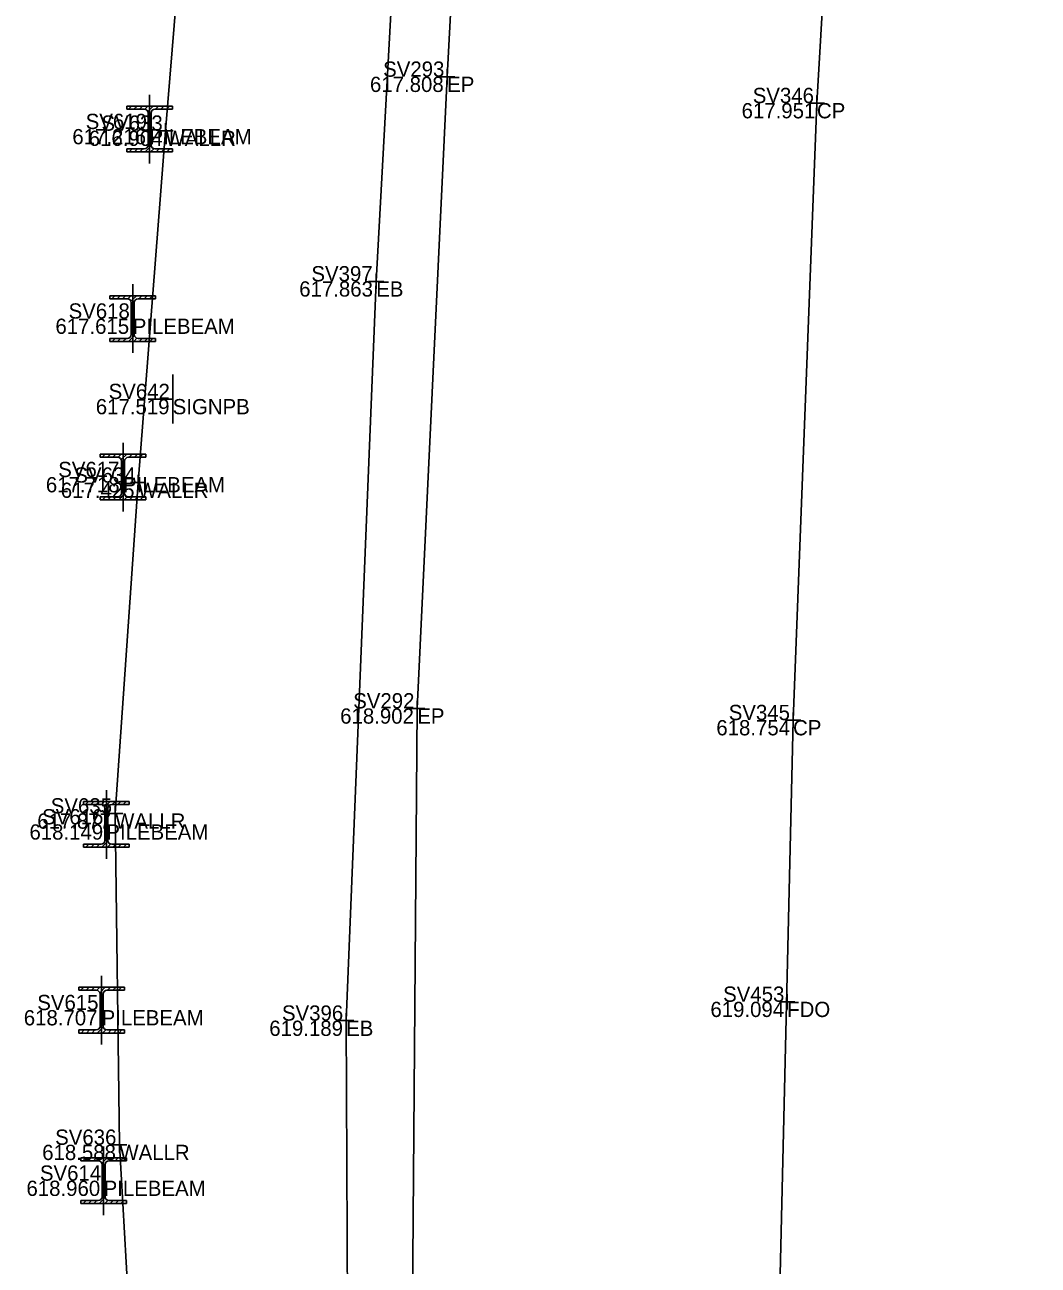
# Model space of a CAD drawing. Extents: x -2 to 1979875, y -2 to 232027.
# Drawn here: x 1978723.28 to 1978756.51, y 230801.2 to 230841.86 of the extents above; entities that cross this region are included whole.
import ezdxf

# ---------------------------------------------------------------- set-up
doc = ezdxf.new("R2010")
doc.units = 0
for name, color, linetype in [('_CIVIL_CONSTRUCTION', 7, 'Continuous'), ('GE_P_Alignment_500_Curve_Data', 7, 'Continuous'), ('GE_X_Alignment', 7, 'Continuous'), ('GE_X_Alignment_1000_Curve_Data', 7, 'Continuous'), ('GE_X_Alignment_1000_Stations', 7, 'Continuous'), ('GE_X_Alignment_100_Curve_Data', 7, 'Continuous'), ('GE_X_Alignment_100_Stations', 7, 'Continuous'), ('GE_X_Alignment_500_Stations', 7, 'Continuous'), ('GT_X_Piling_Cells', 7, 'Continuous'), ('RD_X_Wall', 7, 'Continuous'), ('SC_Scratch1', 7, 'Continuous')]:
    doc.layers.add(name, color=color, linetype=linetype)

msp = doc.modelspace()

# ---------------------------------------------------------------- linework, layer by layer
at = {"layer": 'GE_P_Alignment_500_Curve_Data'}
for p, q in [((1978748.027, 230809.838), (1978748.527, 230809.838)), ((1978748.277, 230810.088), (1978748.277, 230809.588)), ((1978748.277, 230809.838), (1978748.277, 230809.838))]:
    msp.add_line(p, q, dxfattribs=at)
at = {"layer": 'GE_X_Alignment_1000_Curve_Data'}
msp.add_lwpolyline([(1978771.368, 230686.901), (1978762.945, 230707.808), (1978756.184, 230729.845), (1978751.49, 230752.309), (1978748.994, 230772.916), (1978748.08, 230796.049), (1978747.937, 230796.247), (1978748.471, 230819.071), (1978749.254, 230839.296), (1978750.532, 230861.092), (1978751.977, 230883.907), (1978753.538, 230907.259), (1978755.272, 230931.005), (1978756.708, 230952.708), (1978758.182, 230974.871), (1978759.598, 230998.872), (1978761.121, 231023.464)], dxfattribs=at)
at = {"layer": 'GE_X_Alignment_1000_Stations'}
msp.add_lwpolyline([(1978772.336, 230656.843), (1978763.559, 230673.456), (1978754.964, 230693.186), (1978747.098, 230715.323), (1978742.189, 230735.369), (1978738.656, 230754.308), (1978736.533, 230775.816), (1978735.988, 230798.596), (1978736.151, 230819.454), (1978737.13, 230840.16), (1978738.357, 230863.144), (1978739.649, 230887.098), (1978741.331, 230908.702), (1978742.827, 230930.869), (1978744.275, 230952.773), (1978745.794, 230976.041), (1978747.11, 230998.611), (1978748.464, 231019.612), (1978749.988, 231043.472)], dxfattribs=at)
at = {"layer": 'GE_X_Alignment_100_Curve_Data'}
for p, q in [((1978737.13, 230840.41), (1978737.13, 230839.91)), ((1978736.88, 230840.16), (1978737.38, 230840.16)), ((1978737.13, 230840.16), (1978737.13, 230840.16)), ((1978749.254, 230839.546), (1978749.254, 230839.046)), ((1978749.004, 230839.296), (1978749.504, 230839.296)), ((1978749.254, 230839.296), (1978749.254, 230839.296)), ((1978727.645, 230838.391), (1978728.145, 230838.391)), ((1978727.895, 230838.641), (1978727.895, 230838.141)), ((1978727.895, 230838.391), (1978727.895, 230838.391)), ((1978734.555, 230833.453), (1978735.055, 230833.453)), ((1978734.805, 230833.703), (1978734.805, 230833.203)), ((1978734.805, 230833.453), (1978734.805, 230833.453)), ((1978726.998, 230827.105), (1978726.998, 230826.605)), ((1978726.748, 230826.855), (1978727.248, 230826.855)), ((1978726.998, 230826.855), (1978726.998, 230826.855)), ((1978736.151, 230819.704), (1978736.151, 230819.204)), ((1978735.901, 230819.454), (1978736.401, 230819.454)), ((1978736.151, 230819.454), (1978736.151, 230819.454)), ((1978748.471, 230819.321), (1978748.471, 230818.821)), ((1978748.221, 230819.071), (1978748.721, 230819.071)), ((1978748.471, 230819.071), (1978748.471, 230819.071)), ((1978725.994, 230816.011), (1978726.494, 230816.011)), ((1978726.244, 230816.261), (1978726.244, 230815.761)), ((1978726.244, 230816.011), (1978726.244, 230816.011)), ((1978733.819, 230809.469), (1978733.819, 230808.969)), ((1978733.569, 230809.219), (1978734.069, 230809.219)), ((1978733.819, 230809.219), (1978733.819, 230809.219)), ((1978726.384, 230805.4), (1978726.384, 230804.9)), ((1978726.134, 230805.15), (1978726.634, 230805.15)), ((1978726.384, 230805.15), (1978726.384, 230805.15))]:
    msp.add_line(p, q, dxfattribs=at)
at = {"layer": 'GE_X_Alignment_500_Stations'}
for p, q in [((1978728.132, 230830.395), (1978728.132, 230828.795)), ((1978728.132, 230829.595), (1978727.332, 230829.595))]:
    msp.add_line(p, q, dxfattribs=at)
at = {"layer": 'GT_X_Piling_Cells'}
for p, q in [((1978727.374, 230837.32), (1978727.374, 230839.57)), ((1978728.124, 230839.195), (1978726.624, 230839.195)), ((1978726.624, 230839.195), (1978726.624, 230839.095)), ((1978726.624, 230839.095), (1978727.199, 230839.095)), ((1978726.687, 230839.095), (1978726.787, 230839.195)), ((1978726.863, 230839.095), (1978726.963, 230839.195)), ((1978727.04, 230839.095), (1978727.14, 230839.195)), ((1978727.216, 230839.094), (1978727.317, 230839.195)), ((1978727.315, 230839.016), (1978727.494, 230839.195)), ((1978727.549, 230839.095), (1978728.124, 230839.095)), ((1978727.57, 230839.095), (1978727.67, 230839.195)), ((1978727.747, 230839.095), (1978727.847, 230839.195)), ((1978727.924, 230839.095), (1978728.024, 230839.195)), ((1978728.101, 230839.095), (1978728.124, 230839.118)), ((1978728.124, 230839.095), (1978728.124, 230839.195)), ((1978727.324, 230838.97), (1978727.324, 230837.92)), ((1978727.324, 230838.849), (1978727.424, 230838.949)), ((1978727.324, 230838.672), (1978727.424, 230838.772)), ((1978727.424, 230837.92), (1978727.424, 230838.97)), ((1978727.324, 230838.495), (1978727.424, 230838.595)), ((1978727.324, 230838.318), (1978727.424, 230838.418)), ((1978727.374, 230838.445), (1978727.374, 230838.445)), ((1978727.231, 230837.695), (1978727.427, 230837.891)), ((1978727.324, 230838.141), (1978727.424, 230838.241)), ((1978727.324, 230837.965), (1978727.424, 230838.065)), ((1978727.199, 230837.795), (1978726.624, 230837.795)), ((1978726.624, 230837.795), (1978726.624, 230837.695)), ((1978726.624, 230837.695), (1978728.124, 230837.695)), ((1978726.701, 230837.695), (1978726.801, 230837.795)), ((1978726.878, 230837.695), (1978726.978, 230837.795)), ((1978727.054, 230837.695), (1978727.154, 230837.795)), ((1978727.408, 230837.695), (1978727.513, 230837.8)), ((1978728.124, 230837.795), (1978727.549, 230837.795)), ((1978727.585, 230837.695), (1978727.685, 230837.795)), ((1978727.761, 230837.695), (1978727.861, 230837.795)), ((1978727.938, 230837.695), (1978728.038, 230837.795)), ((1978728.115, 230837.695), (1978728.124, 230837.704)), ((1978728.124, 230837.695), (1978728.124, 230837.795)), ((1978727.572, 230832.981), (1978726.072, 230832.981)), ((1978726.072, 230832.981), (1978726.072, 230832.881)), ((1978726.135, 230832.881), (1978726.235, 230832.981)), ((1978726.311, 230832.881), (1978726.411, 230832.981)), ((1978726.488, 230832.881), (1978726.588, 230832.981)), ((1978726.664, 230832.88), (1978726.765, 230832.981)), ((1978726.763, 230832.802), (1978726.942, 230832.981)), ((1978726.822, 230831.106), (1978726.822, 230833.356)), ((1978727.018, 230832.881), (1978727.118, 230832.981)), ((1978727.195, 230832.881), (1978727.295, 230832.981)), ((1978727.372, 230832.881), (1978727.472, 230832.981)), ((1978727.572, 230832.881), (1978727.572, 230832.981)), ((1978726.072, 230832.881), (1978726.647, 230832.881)), ((1978726.772, 230832.756), (1978726.772, 230831.706)), ((1978726.772, 230832.635), (1978726.872, 230832.735)), ((1978726.872, 230831.706), (1978726.872, 230832.756)), ((1978726.997, 230832.881), (1978727.572, 230832.881)), ((1978727.549, 230832.881), (1978727.572, 230832.904)), ((1978726.772, 230832.458), (1978726.872, 230832.558)), ((1978726.772, 230832.281), (1978726.872, 230832.381)), ((1978726.772, 230832.104), (1978726.872, 230832.204)), ((1978726.822, 230832.231), (1978726.822, 230832.231)), ((1978726.772, 230831.927), (1978726.872, 230832.027)), ((1978726.772, 230831.751), (1978726.872, 230831.851)), ((1978726.647, 230831.581), (1978726.072, 230831.581)), ((1978726.072, 230831.581), (1978726.072, 230831.481)), ((1978726.072, 230831.481), (1978727.572, 230831.481)), ((1978726.149, 230831.481), (1978726.249, 230831.581)), ((1978726.326, 230831.481), (1978726.426, 230831.581)), ((1978726.502, 230831.481), (1978726.602, 230831.581)), ((1978726.679, 230831.481), (1978726.875, 230831.677)), ((1978726.856, 230831.481), (1978726.961, 230831.586)), ((1978727.572, 230831.581), (1978726.997, 230831.581)), ((1978727.033, 230831.481), (1978727.133, 230831.581)), ((1978727.209, 230831.481), (1978727.309, 230831.581)), ((1978727.386, 230831.481), (1978727.486, 230831.581)), ((1978727.563, 230831.481), (1978727.572, 230831.49)), ((1978727.572, 230831.481), (1978727.572, 230831.581)), ((1978726.504, 230825.912), (1978726.504, 230828.162)), ((1978727.254, 230827.787), (1978725.754, 230827.787)), ((1978725.754, 230827.787), (1978725.754, 230827.687)), ((1978725.817, 230827.687), (1978725.917, 230827.787)), ((1978725.993, 230827.687), (1978726.093, 230827.787)), ((1978726.17, 230827.687), (1978726.27, 230827.787)), ((1978726.346, 230827.686), (1978726.447, 230827.787)), ((1978726.445, 230827.608), (1978726.624, 230827.787)), ((1978726.7, 230827.687), (1978726.8, 230827.787)), ((1978726.877, 230827.687), (1978726.977, 230827.787)), ((1978727.054, 230827.687), (1978727.154, 230827.787)), ((1978727.231, 230827.687), (1978727.254, 230827.71)), ((1978727.254, 230827.687), (1978727.254, 230827.787)), ((1978725.754, 230827.687), (1978726.329, 230827.687)), ((1978726.454, 230827.562), (1978726.454, 230826.512)), ((1978726.454, 230827.441), (1978726.554, 230827.541)), ((1978726.454, 230827.264), (1978726.554, 230827.364)), ((1978726.554, 230826.512), (1978726.554, 230827.562)), ((1978726.679, 230827.687), (1978727.254, 230827.687)), ((1978726.454, 230827.087), (1978726.554, 230827.187)), ((1978726.454, 230826.91), (1978726.554, 230827.01)), ((1978726.504, 230827.037), (1978726.504, 230827.037)), ((1978726.361, 230826.287), (1978726.557, 230826.483)), ((1978726.454, 230826.733), (1978726.554, 230826.833)), ((1978726.454, 230826.557), (1978726.554, 230826.657)), ((1978726.329, 230826.387), (1978725.754, 230826.387)), ((1978725.754, 230826.387), (1978725.754, 230826.287)), ((1978725.754, 230826.287), (1978727.254, 230826.287)), ((1978725.831, 230826.287), (1978725.931, 230826.387)), ((1978726.008, 230826.287), (1978726.108, 230826.387)), ((1978726.184, 230826.287), (1978726.284, 230826.387)), ((1978726.538, 230826.287), (1978726.643, 230826.392)), ((1978727.254, 230826.387), (1978726.679, 230826.387)), ((1978726.715, 230826.287), (1978726.815, 230826.387)), ((1978726.891, 230826.287), (1978726.991, 230826.387)), ((1978727.068, 230826.287), (1978727.168, 230826.387)), ((1978727.245, 230826.287), (1978727.254, 230826.296)), ((1978727.254, 230826.287), (1978727.254, 230826.387)), ((1978725.957, 230814.528), (1978725.957, 230816.778)), ((1978726.707, 230816.403), (1978725.207, 230816.403)), ((1978725.207, 230816.403), (1978725.207, 230816.303)), ((1978725.27, 230816.303), (1978725.37, 230816.403)), ((1978725.446, 230816.303), (1978725.546, 230816.403)), ((1978725.623, 230816.303), (1978725.723, 230816.403)), ((1978725.799, 230816.302), (1978725.9, 230816.403)), ((1978725.898, 230816.224), (1978726.077, 230816.403)), ((1978726.153, 230816.303), (1978726.253, 230816.403)), ((1978726.33, 230816.303), (1978726.43, 230816.403)), ((1978726.507, 230816.303), (1978726.607, 230816.403)), ((1978726.684, 230816.303), (1978726.707, 230816.326)), ((1978726.707, 230816.303), (1978726.707, 230816.403)), ((1978725.207, 230816.303), (1978725.782, 230816.303)), ((1978725.907, 230816.178), (1978725.907, 230815.128)), ((1978725.907, 230816.057), (1978726.007, 230816.157)), ((1978725.907, 230815.88), (1978726.007, 230815.98)), ((1978726.007, 230815.128), (1978726.007, 230816.178)), ((1978726.132, 230816.303), (1978726.707, 230816.303)), ((1978725.907, 230815.703), (1978726.007, 230815.803)), ((1978725.907, 230815.526), (1978726.007, 230815.626)), ((1978725.957, 230815.653), (1978725.957, 230815.653)), ((1978725.814, 230814.903), (1978726.01, 230815.099)), ((1978725.907, 230815.349), (1978726.007, 230815.449)), ((1978725.907, 230815.173), (1978726.007, 230815.273)), ((1978725.782, 230815.003), (1978725.207, 230815.003)), ((1978725.207, 230815.003), (1978725.207, 230814.903)), ((1978725.207, 230814.903), (1978726.707, 230814.903)), ((1978725.284, 230814.903), (1978725.384, 230815.003)), ((1978725.461, 230814.903), (1978725.561, 230815.003)), ((1978725.637, 230814.903), (1978725.737, 230815.003)), ((1978725.991, 230814.903), (1978726.096, 230815.008)), ((1978726.707, 230815.003), (1978726.132, 230815.003)), ((1978726.168, 230814.903), (1978726.268, 230815.003)), ((1978726.344, 230814.903), (1978726.444, 230815.003)), ((1978726.521, 230814.903), (1978726.621, 230815.003)), ((1978726.698, 230814.903), (1978726.707, 230814.912)), ((1978726.707, 230814.903), (1978726.707, 230815.003)), ((1978725.801, 230808.439), (1978725.801, 230810.689)), ((1978726.551, 230810.314), (1978725.051, 230810.314)), ((1978725.051, 230810.314), (1978725.051, 230810.214)), ((1978725.051, 230810.214), (1978725.626, 230810.214)), ((1978725.114, 230810.214), (1978725.214, 230810.314)), ((1978725.29, 230810.214), (1978725.39, 230810.314)), ((1978725.467, 230810.214), (1978725.567, 230810.314)), ((1978725.643, 230810.213), (1978725.744, 230810.314)), ((1978725.742, 230810.135), (1978725.921, 230810.314)), ((1978725.976, 230810.214), (1978726.551, 230810.214)), ((1978725.997, 230810.214), (1978726.097, 230810.314)), ((1978726.174, 230810.214), (1978726.274, 230810.314)), ((1978726.351, 230810.214), (1978726.451, 230810.314)), ((1978726.528, 230810.214), (1978726.551, 230810.237)), ((1978726.551, 230810.214), (1978726.551, 230810.314)), ((1978725.751, 230810.089), (1978725.751, 230809.039)), ((1978725.751, 230809.968), (1978725.851, 230810.068)), ((1978725.751, 230809.791), (1978725.851, 230809.891)), ((1978725.851, 230809.039), (1978725.851, 230810.089)), ((1978725.751, 230809.614), (1978725.851, 230809.714)), ((1978725.751, 230809.437), (1978725.851, 230809.537)), ((1978725.801, 230809.564), (1978725.801, 230809.564)), ((1978725.658, 230808.814), (1978725.854, 230809.01)), ((1978725.751, 230809.26), (1978725.851, 230809.36)), ((1978725.751, 230809.084), (1978725.851, 230809.184)), ((1978725.626, 230808.914), (1978725.051, 230808.914)), ((1978725.051, 230808.914), (1978725.051, 230808.814)), ((1978725.051, 230808.814), (1978726.551, 230808.814)), ((1978725.128, 230808.814), (1978725.228, 230808.914)), ((1978725.305, 230808.814), (1978725.405, 230808.914)), ((1978725.481, 230808.814), (1978725.581, 230808.914)), ((1978725.835, 230808.814), (1978725.94, 230808.919)), ((1978726.551, 230808.914), (1978725.976, 230808.914)), ((1978726.012, 230808.814), (1978726.112, 230808.914)), ((1978726.188, 230808.814), (1978726.288, 230808.914)), ((1978726.365, 230808.814), (1978726.465, 230808.914)), ((1978726.542, 230808.814), (1978726.551, 230808.823)), ((1978726.551, 230808.814), (1978726.551, 230808.914)), ((1978725.868, 230802.848), (1978725.868, 230805.098)), ((1978726.618, 230804.723), (1978725.118, 230804.723)), ((1978725.118, 230804.723), (1978725.118, 230804.623)), ((1978725.118, 230804.623), (1978725.693, 230804.623)), ((1978725.181, 230804.623), (1978725.281, 230804.723)), ((1978725.357, 230804.623), (1978725.457, 230804.723)), ((1978725.534, 230804.623), (1978725.634, 230804.723)), ((1978725.71, 230804.622), (1978725.811, 230804.723)), ((1978725.809, 230804.544), (1978725.988, 230804.723)), ((1978726.043, 230804.623), (1978726.618, 230804.623)), ((1978726.064, 230804.623), (1978726.164, 230804.723)), ((1978726.241, 230804.623), (1978726.341, 230804.723)), ((1978726.418, 230804.623), (1978726.518, 230804.723)), ((1978726.595, 230804.623), (1978726.618, 230804.646)), ((1978726.618, 230804.623), (1978726.618, 230804.723)), ((1978725.818, 230804.498), (1978725.818, 230803.448)), ((1978725.818, 230804.377), (1978725.918, 230804.477)), ((1978725.818, 230804.2), (1978725.918, 230804.3)), ((1978725.818, 230804.023), (1978725.918, 230804.123)), ((1978725.918, 230803.448), (1978725.918, 230804.498)), ((1978725.818, 230803.846), (1978725.918, 230803.946)), ((1978725.818, 230803.669), (1978725.918, 230803.769)), ((1978725.868, 230803.973), (1978725.868, 230803.973)), ((1978725.693, 230803.323), (1978725.118, 230803.323)), ((1978725.118, 230803.323), (1978725.118, 230803.223)), ((1978725.195, 230803.223), (1978725.295, 230803.323)), ((1978725.372, 230803.223), (1978725.472, 230803.323)), ((1978725.548, 230803.223), (1978725.648, 230803.323)), ((1978725.725, 230803.223), (1978725.921, 230803.419)), ((1978725.818, 230803.493), (1978725.918, 230803.593)), ((1978725.902, 230803.223), (1978726.007, 230803.328)), ((1978726.618, 230803.323), (1978726.043, 230803.323)), ((1978726.079, 230803.223), (1978726.179, 230803.323)), ((1978726.255, 230803.223), (1978726.355, 230803.323)), ((1978726.432, 230803.223), (1978726.532, 230803.323)), ((1978726.618, 230803.223), (1978726.618, 230803.323)), ((1978725.118, 230803.223), (1978726.618, 230803.223)), ((1978726.609, 230803.223), (1978726.618, 230803.232))]:
    msp.add_line(p, q, dxfattribs=at)
for centre, start, end in [((1978727.199, 230838.97), 0, 90), ((1978727.549, 230838.97), 90, 180), ((1978727.199, 230837.92), 270, 0), ((1978727.549, 230837.92), 180, 270), ((1978726.647, 230832.756), 0, 90), ((1978726.997, 230832.756), 90, 180), ((1978726.647, 230831.706), 270, 0), ((1978726.997, 230831.706), 180, 270), ((1978726.329, 230827.562), 0, 90), ((1978726.679, 230827.562), 90, 180), ((1978726.329, 230826.512), 270, 0), ((1978726.679, 230826.512), 180, 270), ((1978725.782, 230816.178), 0, 90), ((1978726.132, 230816.178), 90, 180), ((1978725.782, 230815.128), 270, 0), ((1978726.132, 230815.128), 180, 270), ((1978725.626, 230810.089), 0, 90), ((1978725.976, 230810.089), 90, 180), ((1978725.626, 230809.039), 270, 0), ((1978725.976, 230809.039), 180, 270), ((1978725.693, 230804.498), 0, 90), ((1978726.043, 230804.498), 90, 180), ((1978725.693, 230803.448), 270, 0), ((1978726.043, 230803.448), 180, 270)]:
    msp.add_arc(centre, 0.125, start, end, dxfattribs=at)
at = {"layer": 'RD_X_Wall'}
msp.add_lwpolyline([(1978732.056, 230886.781), (1978731.746, 230883.073), (1978731.431, 230882.716), (1978730.487, 230868.646), (1978729.395, 230856.593), (1978727.895, 230838.391), (1978726.998, 230826.855), (1978726.244, 230816.011), (1978726.384, 230805.15), (1978727.259, 230789.767), (1978727.515, 230778.19), (1978728.731, 230764.777), (1978729.78, 230755.535)], dxfattribs=at)
at = {"layer": 'SC_Scratch1'}
msp.add_lwpolyline([(1978770.288, 230655.73), (1978760.891, 230674.584), (1978752.193, 230695.227), (1978744.942, 230716.175), (1978738.905, 230740.874), (1978735.553, 230763.886), (1978733.918, 230787.98), (1978733.819, 230809.219), (1978734.805, 230833.453), (1978736.148, 230858.007), (1978737.85, 230882.597), (1978739.105, 230905.756), (1978740.693, 230929.953), (1978742.419, 230953.633), (1978743.494, 230976.312), (1978745.216, 230999.029), (1978746.767, 231023.392)], dxfattribs=at)

# ---------------------------------------------------------------- texts
at = {"layer": '_CIVIL_CONSTRUCTION'}
for s, p in [('617.808', (1978734.6, 230839.66)), ('617.951', (1978746.784, 230838.796)), ('617.216', (1978724.842, 230837.945)), ('616.904', (1978725.379, 230837.891)), ('617.863', (1978732.28, 230832.953)), ('617.615', (1978724.287, 230831.731)), ('617.519', (1978725.611, 230829.095)), ('617.718', (1978723.974, 230826.537)), ('617.425', (1978724.463, 230826.355)), ('618.902', (1978733.623, 230818.954)), ('618.754', (1978745.955, 230818.571)), ('617.877', (1978723.693, 230815.511)), ('618.149', (1978723.436, 230815.153)), ('619.094', (1978745.761, 230809.338)), ('618.707', (1978723.25, 230809.064)), ('619.189', (1978731.298, 230808.719)), ('618.588', (1978723.854, 230804.65)), ('618.960', (1978723.338, 230803.473))]:
    msp.add_text(s, height=0.5, dxfattribs=at).set_placement(p)
at = {"layer": 'GE_X_Alignment'}
for s, p in [('SV293', (1978735.032, 230840.16)), ('SV346', (1978747.149, 230839.296)), ('SV619', (1978725.28, 230838.445)), ('SV633', (1978725.797, 230838.391)), ('SV397', (1978732.68, 230833.453)), ('SV618', (1978724.719, 230832.231)), ('SV642', (1978726.031, 230829.595)), ('SV617', (1978724.379, 230827.037)), ('SV634', (1978724.909, 230826.855)), ('SV292', (1978734.05, 230819.454)), ('SV345', (1978746.362, 230819.071)), ('SV635', (1978724.135, 230816.011)), ('SV616', (1978723.852, 230815.653)), ('SV453', (1978746.179, 230809.838)), ('SV615', (1978723.692, 230809.564)), ('SV396', (1978731.714, 230809.219)), ('SV636', (1978724.279, 230805.15)), ('SV614', (1978723.779, 230803.973))]:
    msp.add_text(s, height=0.5, dxfattribs=at).set_placement(p)
at = {"layer": 'GE_X_Alignment_100_Stations'}
for s, p in [('EP', (1978737.13, 230839.66)), ('CP', (1978749.254, 230838.796)), ('PILEBEAM', (1978727.374, 230837.945)), ('WALLR', (1978727.895, 230837.891)), ('EB', (1978734.805, 230832.953)), ('PILEBEAM', (1978726.822, 230831.731)), ('SIGNPB', (1978728.132, 230829.095)), ('PILEBEAM', (1978726.504, 230826.537)), ('WALLR', (1978726.998, 230826.355)), ('EP', (1978736.151, 230818.954)), ('CP', (1978748.471, 230818.571)), ('WALLR', (1978726.244, 230815.511)), ('PILEBEAM', (1978725.957, 230815.153)), ('FDO', (1978748.277, 230809.338)), ('PILEBEAM', (1978725.801, 230809.064)), ('EB', (1978733.819, 230808.719)), ('WALLR', (1978726.384, 230804.65)), ('PILEBEAM', (1978725.868, 230803.473))]:
    msp.add_text(s, height=0.5, dxfattribs=at).set_placement(p)

doc.saveas('drawing.dxf')
